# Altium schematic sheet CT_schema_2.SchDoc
size 382 x 218 mm
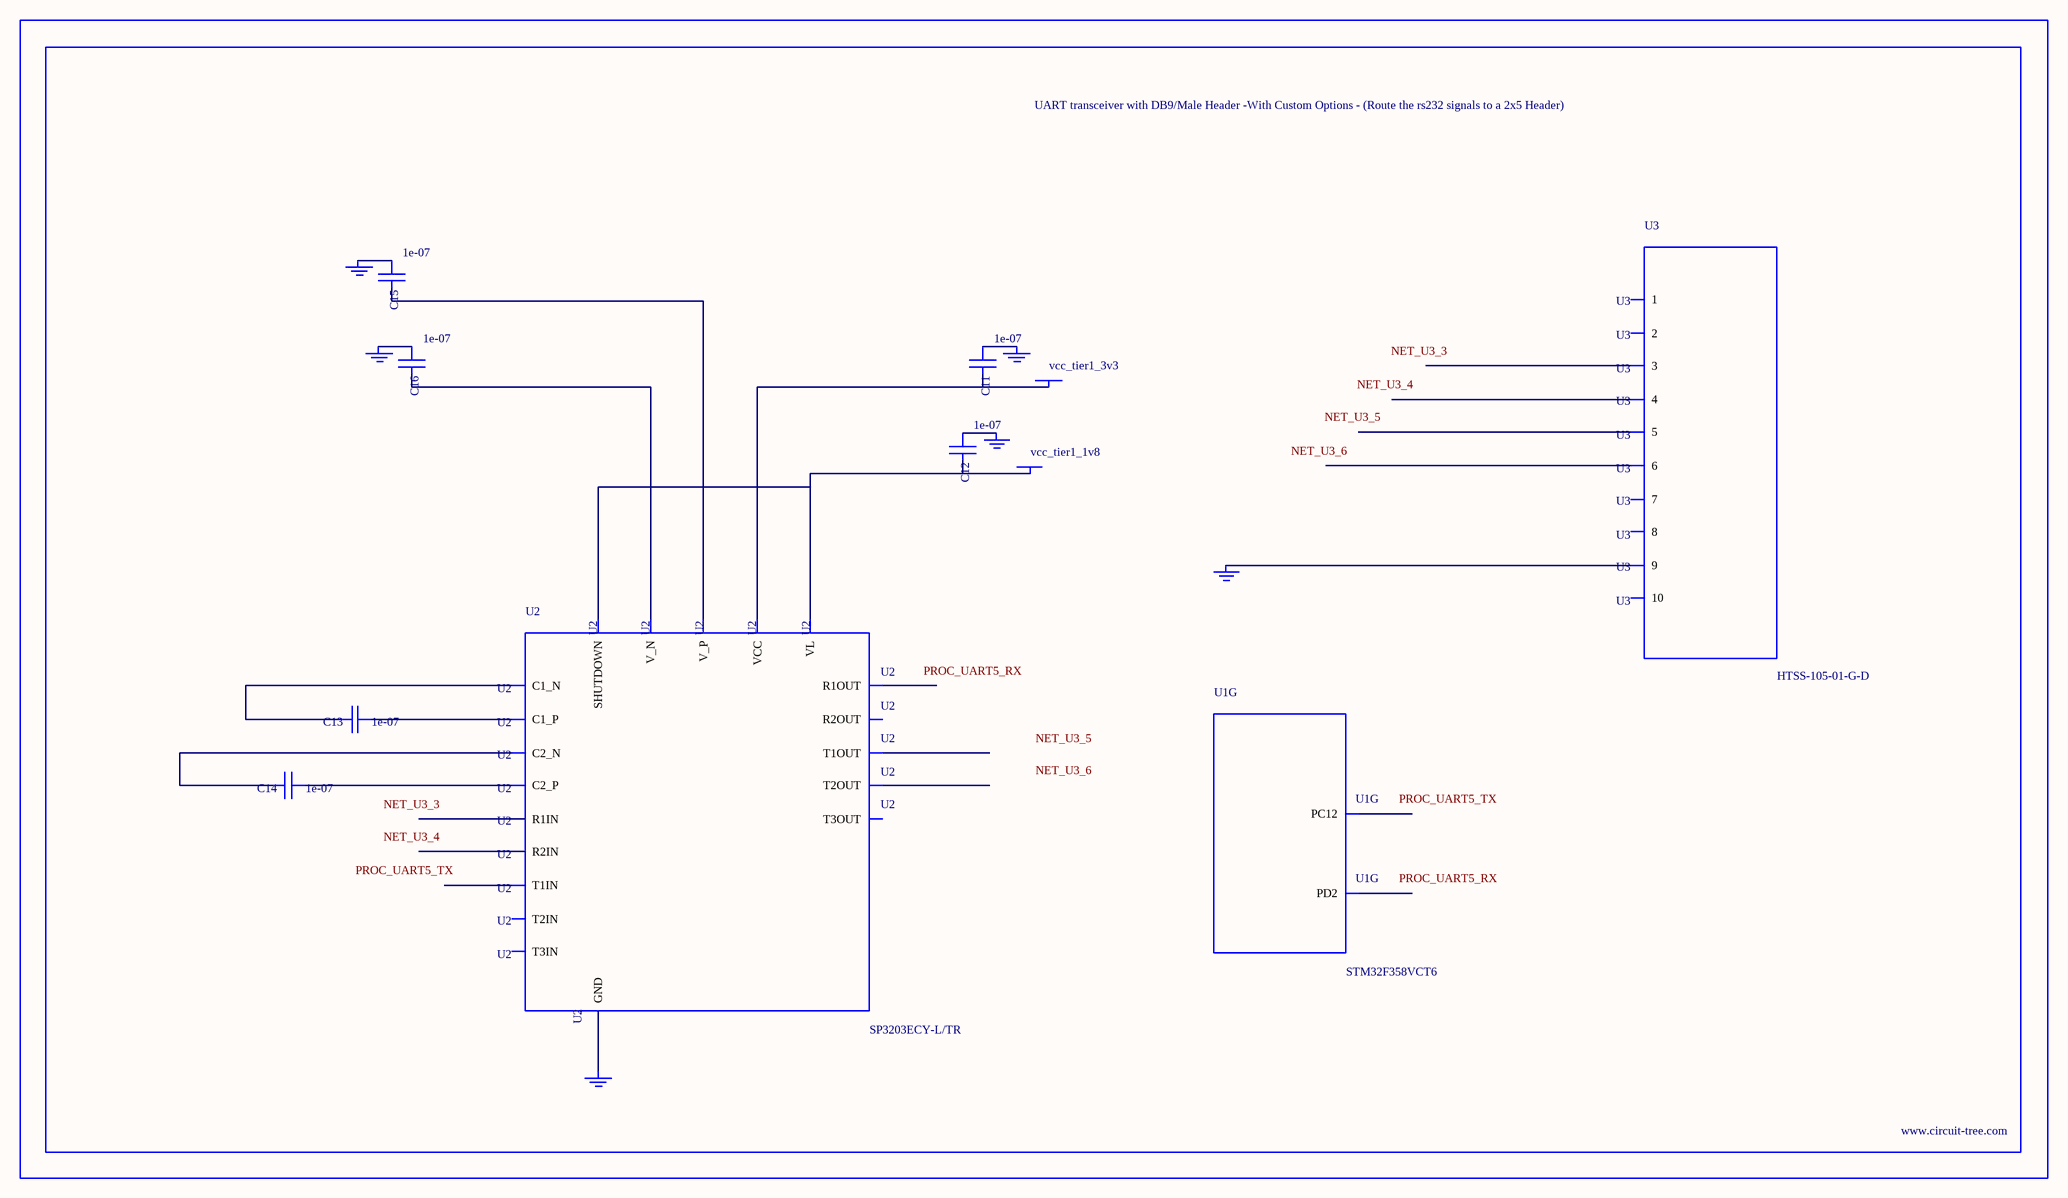
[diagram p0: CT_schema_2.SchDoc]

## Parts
BORDER1  (no value)
C11  1e-07  [C0402]
C12  1e-07  [C0402]
C13  1e-07  [C0402]
C14  1e-07  [C0402]
C15  1e-07  [C0402]
C16  1e-07  [C0402]
GND_INSTANCE_1_0  (no value)
GND_INSTANCE_1_1  (no value)
GND_INSTANCE_1_2  (no value)
GND_INSTANCE_1_3  (no value)
GND_INSTANCE_1_4  (no value)
GND_INSTANCE_1_5  (no value)
POWER_INSTANCE_1_0  vcc_tier1_1v8
POWER_INSTANCE_1_1  vcc_tier1_3v3
U1  STM32F358VCT6  [LQFP100]  (part G of 10)
U2  SP3203ECY-L/TR  [TSSOP20-I]
U3  HTSS-105-01-G-D  [HTSS-105-01-G-D]

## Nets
NetC11_1: C11.1 GND_INSTANCE_1_3.0(GND)
NetC11_2: C11.2 POWER_INSTANCE_1_1.0(PWR) U2.19(VCC)
NetC12_1: C12.1 GND_INSTANCE_1_2.0(GND)
NetC12_2: C12.2 POWER_INSTANCE_1_0.0(PWR) U2.12(VL) U2.20(SHUTDOWN)
NetC13_1: C13.1 U2.1(C1_P)
NetC13_2: C13.2 U2.3(C1_N)
NetC14_1: C14.1 U2.4(C2_P)
NetC14_2: C14.2 U2.5(C2_N)
NetC15_1: C15.1 GND_INSTANCE_1_0.0(GND)
NetC15_2: C15.2 U2.2(V_P)
NetC16_1: C16.1 GND_INSTANCE_1_1.0(GND)
NetC16_2: C16.2 U2.6(V_N)
NetGND_INSTANCE_1_4_0: GND_INSTANCE_1_4.0(GND) U2.18(GND)
NetGND_INSTANCE_1_5_0: GND_INSTANCE_1_5.0(GND) U3.9

Not connected (* = marked no-connect by the designer): U1 80(PC12) 83(PD2); U2 7(T1IN) 8(T2IN) 9(T3IN) 10(R2OUT) 11(R1OUT) 13(R2IN) 14(R1IN) 15(T3OUT) 16(T2OUT) 17(T1OUT); U3 1 2 3 4 5 6 7 8 10

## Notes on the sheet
- Labels drawn without touching a wire or pin: NET_U3_3, NET_U3_4, NET_U3_5, NET_U3_6, PROC_UART5_RX, PROC_UART5_TX

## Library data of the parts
BORDER1 = BORDER_PAGE1
C11-C16 = C0402C104K3RACTU
GND_INSTANCE_1_0-GND_INSTANCE_1_5 = GND
POWER_INSTANCE_1_0 POWER_INSTANCE_1_1 = PWR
